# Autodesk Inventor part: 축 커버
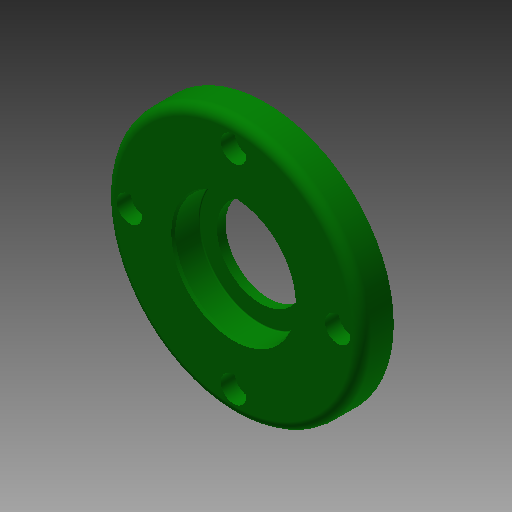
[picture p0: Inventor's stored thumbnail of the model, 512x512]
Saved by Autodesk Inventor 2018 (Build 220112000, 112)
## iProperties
Created: 2015-10
Part Number: 축 커버
Document SubType Name: Modeling
Designer: mdu
Density: 1 g/cm^3
Material: 일반
Appearance: 진녹색
Author: mdu
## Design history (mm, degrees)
sketch "스케치1"
  geometry: C1 r 40 at (0, 0) reference; C2 r 26 at (0, 0) reference; 1 further point
  node "참조1"
  node "참조2"
extrude "돌출1" new body sketch "스케치1" distance "d0" = 10; taper "d1" = 0 deg
extrude "돌출2" join sketch "스케치1" distance "d2" = 4; taper "d3" = 0 deg
hole "구멍1" diameter "d6" = 27; stored, may be unused: countersink angle "d10" = 90 deg, drill point angle "d12" = 118 deg; dims "d7" = 6, "d8" = 38, "d9" = 8.3, "d11" = 8, "d33" = 10, "d34" = 10
sketch "스케치2"
  geometry: C1 r 20 at (0, 0); 1 further point
  constraints: 1 centre point, 1 coincident
  dimensions: "d13" = 40 diameter of C1
extrude "돌출3" cut sketch "스케치2" distance "d14" = 3; taper "d15" = 0 deg
sketch "스케치3"
  geometry: C1 r 1.621 at (0, 32.5) reference; 1 further point
hole "구멍2" sketch "스케치3" at (0, 32.5) diameter "d16" = 4.5; stored, may be unused: countersink angle "d20" = 90 deg, drill point angle "d22" = 118 deg; dims "d17" = 6, "d18" = 8, "d19" = 4.4, "d21" = 8
fillet "모깎기1" dims "d26" = 3, "d27" = 0.3
chamfer "모따기1" distance "d28" = 1; stored, may be unused: second distance "d29" = 2, angle "d30" = 45 deg
chamfer "모따기2" distance "d31" = 0.8; stored, may be unused: second distance "d32" = 2, angle "d35" = 30 deg
node "솔리드1"
pattern_circular "원형 패턴1" dims angle "d24" = 360 deg
node "참조3"
